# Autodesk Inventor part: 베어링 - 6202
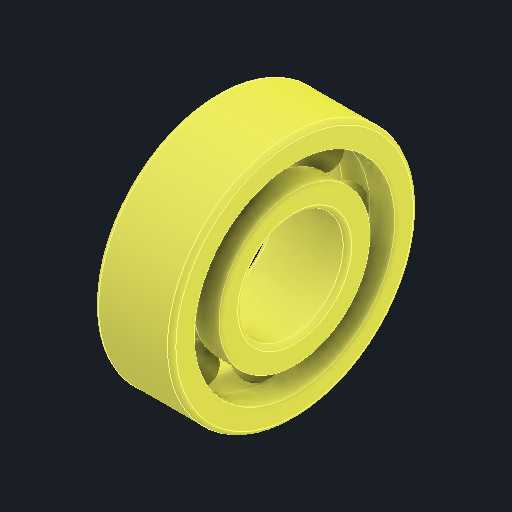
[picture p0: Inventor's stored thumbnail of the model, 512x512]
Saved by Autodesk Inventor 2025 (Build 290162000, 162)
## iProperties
Created: 2025-08
Part Number: 베어링 - 6202
Material: 강, 연강
Description: 깊은 그루브 볼 베어링
Document SubType Name: Modeling
Designer: infra006
Density: 7.86 g/cm^3
Appearance: 기본값
Author: jhkim
Sending System: Autodesk Inventor 2026
Preprocessor: ST-DEVELOPER v20.1
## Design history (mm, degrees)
feature "Solid1"
feature "Solid1:1"
feature "Solid1:2"
feature "Solid1:3"
feature "Solid1:4"
feature "Solid1:5"
feature "Solid1:6"
feature "Solid1:7"
feature "Solid1:8"
feature "Solid1:9"
node "솔리드1"
node "솔리드2"
node "솔리드3"
node "솔리드4"
node "솔리드5"
node "솔리드6"
node "솔리드7"
node "솔리드8"
node "솔리드9"
node "솔리드10"
